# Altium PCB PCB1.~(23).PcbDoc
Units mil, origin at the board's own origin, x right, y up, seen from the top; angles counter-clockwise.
Board outline 6000 x 4000 mil, 2 copper layers (Top Layer, Bottom Layer); 33 components, 28 nets, 150 pads, 4 vias.
Unrouted connection lines stored in the file: 64.
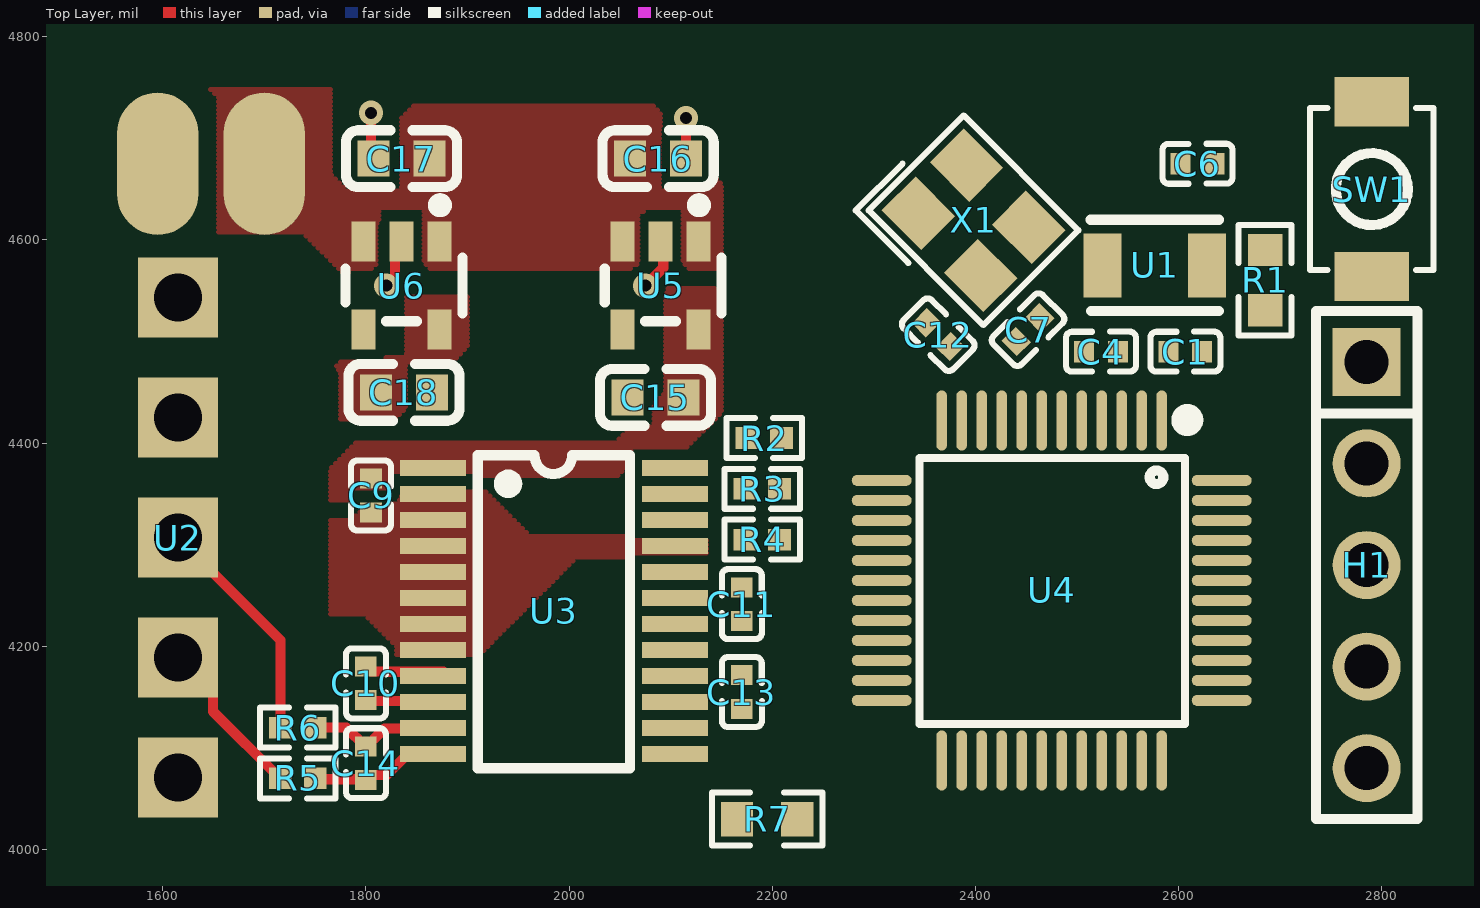
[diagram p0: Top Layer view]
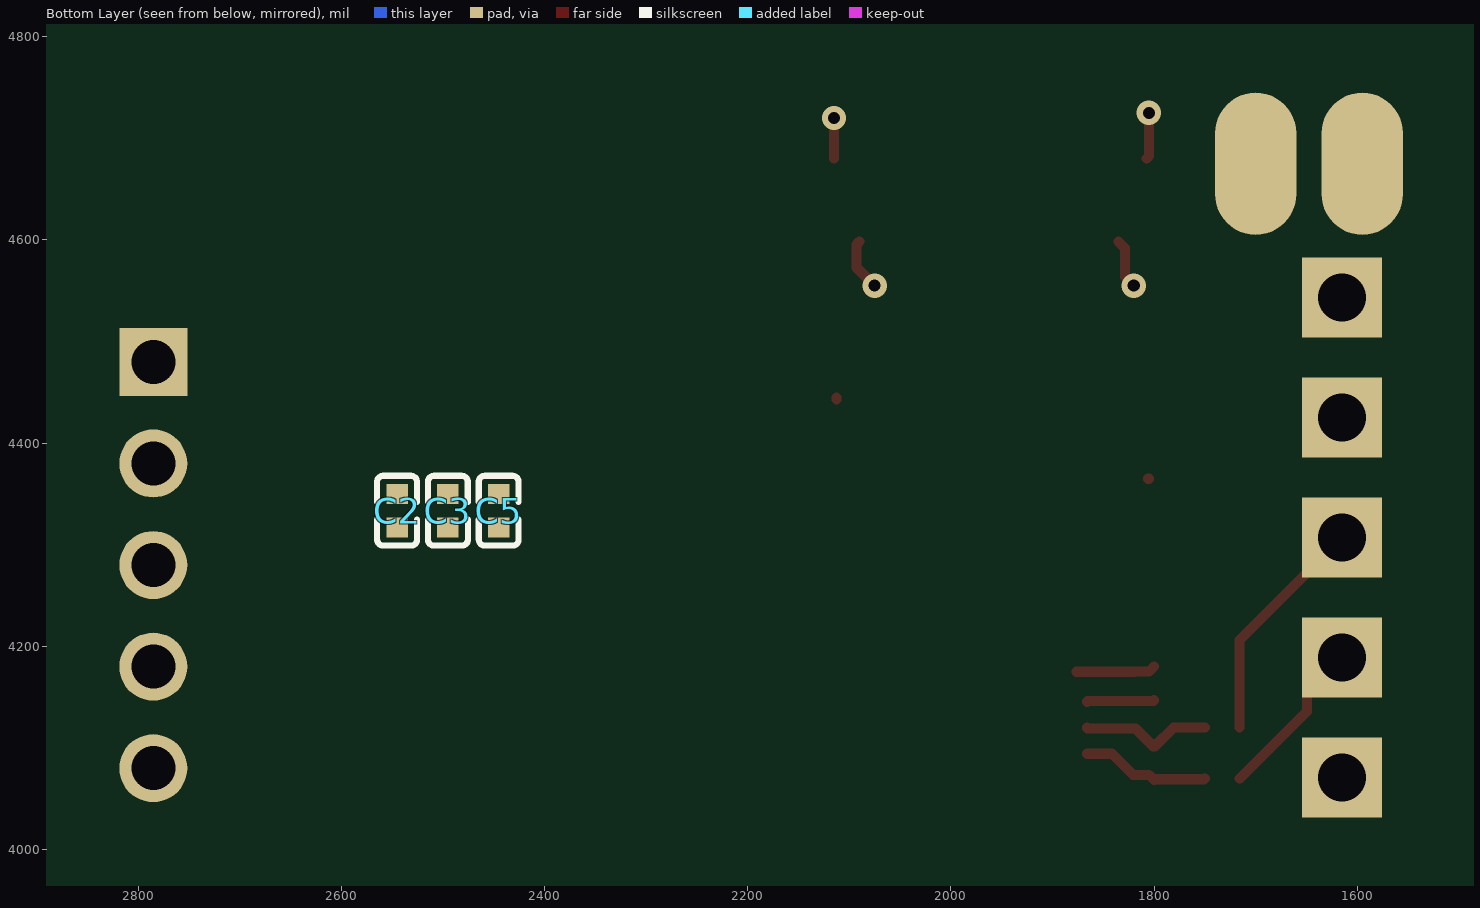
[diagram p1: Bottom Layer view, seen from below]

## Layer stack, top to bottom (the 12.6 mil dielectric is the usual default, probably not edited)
Top Solder: solder mask 0.4, Solder Resist, Dk 3.5
Top Layer: signal copper 1.4
Dielectric 1: dielectric 12.6, FR-4, Dk 4.8
Bottom Layer: signal copper 1.4
Bottom Solder: solder mask 0.4, Solder Resist, Dk 3.5

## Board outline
1000,1000 7000,1000 7000,5000 1000,5000

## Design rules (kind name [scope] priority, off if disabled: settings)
Clearance [All] p1: gap=8 ignorepadtopadclearanceinfootprint=FALSE
ComponentClearance [All] p1: gap=0 collisioncheckmode=3 verticalgap=0 showdistances=FALSE
MinimumSolderMaskSliver [All] p1: minsoldermaskwidth=4
PlaneConnect [All] p1: planeconnectstyle=Direct reliefexpansion=20 reliefentries=4 reliefconductorwidth=10 reliefairgap=10
PolygonConnect [All] p1: connectstyle=Direct reliefconductorwidth=10 reliefentries=4 polygonreliefangle="90 Angle" airgapwidth=10
RoutingVias [All] p1: holewidth=28 width=50 viastyle="Through Hole" minholewidth=28 minwidth=50 maxholewidth=28 maxwidth=50
SilkToSilkClearance [All] p1: silktosilkclearance=5
SilkToSolderMaskClearance [IsPad] p1: minsilkscreentomaskgap=5 clearancetoexposedcopper=TRUE
SolderMaskExpansion [All] p1: expansion=0 istentingtop=FALSE
SupplyNets "Schematic Supply Nets_2" [InNet('6V')] p1: voltage=0.000
SupplyNets "Schematic Supply Nets" [InNet('3V3')] p2: voltage=0.000
SupplyNets "Schematic Supply Nets_4" [InNet('5V')] p3: voltage=0.000
SupplyNets "Schematic Supply Nets_3" [InNet('DGND')] p4: voltage=0.000
SupplyNets "Schematic Supply Nets_1" [InNet('AGND')] p5: voltage=0.000
Width [All] p1: maxlimit=10 minlimit=10 preferedwidth=10
25 further rules are at their usual default settings.

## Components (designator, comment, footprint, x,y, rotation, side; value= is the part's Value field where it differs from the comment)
C1 "cc0402jrnpo9bn220" C0402 2606.54,4490 r180 top value=22pF
C2 "cc0402krx7r7bb104" C0402 2545,4333.46 r270 bottom value=100nF
C3 "cc0402krx7r7bb104" C0402 2495,4333.46 r90 bottom value=100nF
C4 "cc0402jrnpo9bn220" C0402 2523.46,4490 r0 top value=22pF
C5 "cc0402krx7r7bb104" C0402 2445,4333.46 r270 bottom value=100nF
C6 "cc0402krx7r7bb104" C0402 2618.46,4675 r0 top value=100nF
C7 "cc0402jrnpo9bn180" C0402 2451.7,4511.7 r45 top value=18pF
C9 "cc0402krx7r7bb104" C0402 1805,4348.46 r270 top value=100nF
C10 "cc0402krx7r7bb104" C0402 1800,4163.46 r90 top value=100nF
C11 "cc0402krx7r7bb104" C0402 2170,4241.54 r90 top value=100nF
C12 "cc0402jrnpo9bn180" C0402 2363.3,4506.7 r315 top value=18pF
C13 "gcm155r71h103ka55d" C0402 2170,4155 r270 top value=10nF
C14 "gcm155r71h103ka55d" C0402 1800,4085 r270 top value=10nF
C15 "cga0603x5r105k500jt" C0603 2085,4445 r180 top value=1uF
C16 "cga0603x5r105k500jt" C0603 2087.56,4680 r0 top value=1uF
C17 "cga0603x5r105k500jt" C0603 1835,4680 r180 top value=1uF
C18 "cga0603x5r105k500jt" C0603 1837.44,4450 r0 top value=1uF
H1 "pz254v-11-05p" HDR-TH_5P-P2.54-V-M 2785,4280 r270 top
R1 "frc0603f1002ts" R0603 2685,4560.34 r270 top value=10kΩ
R2 "frc0402f47r0ts" R0402 2192.04,4405 r0 top value=47Ω
R3 "frc0402f47r0ts" R0402 2190,4355 r0 top value=47Ω
R4 "frc0402f47r0ts" R0402 2190,4305 r0 top value=47Ω
R5 "frc0402f1000ts" R0402 1732.96,4070 r0 top value=100Ω
R6 "frc0402f1000ts" R0402 1732.96,4120 r0 top value=100Ω
R7 "0603waf0000t5e" R0603 2195,4030 r0 top value=0Ω
SW1 "ts-1088-ar02016" SW-SMD_L3.9-W3.0-P4.45 2790,4650 r90 top
U1 "fc31m2-32.768-ntlnndtl" CRYSTAL-SMD_L3.2-W1.5 2576.5,4575 r180 top value=32.768kHz
U2 "5个焊盘" 5个焊盘 1615,4543.1 r270 top
U3 "ads1232ipwr" TSSOP-24_L7.8-W4.4-P0.65-LS6.4-BL 1985,4235 r270 top
U4 "stm32g031c8t6" LQFP-48_L7.0-W7.0-P0.50-LS9.0-BL 2475,4255 r180 top
U5 "tps7a2033pdbvr" SOT-23-5_L2.9-W1.6-P0.95-LS2.8-BR 2090,4555 r90 top
U6 "tps7a2050pdbvr" SOT-23-5_L2.9-W1.6-P0.95-LS2.8-BR 1835,4555 r90 top
X1 "x32258mob4si" CRYSTAL-SMD_4P-L3.2-W2.5-BL 2398.04,4619.29 r315 top value=8MHz

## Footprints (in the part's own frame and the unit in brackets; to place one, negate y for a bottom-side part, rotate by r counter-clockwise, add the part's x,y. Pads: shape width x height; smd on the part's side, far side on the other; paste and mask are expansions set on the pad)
5个焊盘 [mm]
  rect 2x2 hole 1.2: 1(0,0) 2(3,0) 3(6.001,0) 4(9,0) 5(12,0)
C0402 [mm]
  rect 0.5x0.54 smd: 1(-0.42,0) 2(0.42,0)
  silkscreen extent -0.87,-0.5 0.87,0.5
C0603 [mm]
  rect 0.8x0.9 smd: 1(-0.7,0) 2(0.7,0)
  silkscreen extent -1.39,-0.71 1.39,0.71
CRYSTAL-SMD_4P-L3.2-W2.5-BL [mm]
  rect 1.4x1.2 smd: 1(-1.1,-0.85) 2(1.1,-0.85) 3(1.1,0.85) 4(-1.1,0.85)
  silkscreen extent -2.26,-1.91 2.03,1.68
CRYSTAL-SMD_L3.2-W1.5 [mm]
  rect 0.95x1.6 smd: 1(-1.308,0) 2(1.308,0)
  silkscreen extent -1.6,-1.14 1.6,1.14
HDR-TH_5P-P2.54-V-M [mm]
  rect 1.7x1.7 hole 1.1: 1(-5.08,0)
  round 1.7 hole 1.1: 2(-2.54,0) 3(0,0) 4(2.54,0) 5(5.08,0)
  silkscreen extent -6.35,-1.27 6.35,1.27
LQFP-48_L7.0-W7.0-P0.50-LS9.0-BL [mm]
  oval 0.27x1.5 smd paste+0 mask+0.05: 1(-2.75,-4.25) 2(-2.25,-4.25) 3(-1.75,-4.25) 4(-1.25,-4.25) 5(-0.75,-4.25) 6(-0.25,-4.25) 7(0.25,-4.25) 8(0.75,-4.25) 9(1.25,-4.25) 10(1.75,-4.25) 11(2.25,-4.25) 12(2.75,-4.25) 25(2.75,4.25) 26(2.25,4.25) 27(1.75,4.25) 28(1.25,4.25) 29(0.75,4.25) 30(0.25,4.25) 31(-0.25,4.25) 32(-0.75,4.25) 33(-1.25,4.25) 34(-1.75,4.25) 35(-2.25,4.25) 36(-2.75,4.25)
  oval 1.5x0.27 smd paste+0 mask+0.05: 13(4.25,-2.75) 14(4.25,-2.25) 15(4.25,-1.75) 16(4.25,-1.25) 17(4.25,-0.75) 18(4.25,-0.25) 19(4.25,0.25) 20(4.25,0.75) 21(4.25,1.25) 22(4.25,1.75) 23(4.25,2.25) 24(4.25,2.75) 37(-4.25,2.75) 38(-4.25,2.25) 39(-4.25,1.75) 40(-4.25,1.25) 41(-4.25,0.75) 42(-4.25,0.25) 43(-4.25,-0.25) 44(-4.25,-0.75) 45(-4.25,-1.25) 46(-4.25,-1.75) 47(-4.25,-2.25) 48(-4.25,-2.75)
  silkscreen extent -3.59,-4.46 3.3,3.34
R0402 [mm]
  rect 0.566x0.54 smd paste-100 mask+0.051: 1(-0.433,0) 2(0.433,0)
  silkscreen extent -0.94,-0.5 0.94,0.5
R0603 [mil]
  rect 31.75x34.02 smd paste-3937.01 mask+2: 1(-29.66,0) 2(29.66,0)
  silkscreen extent -55,-26 55,26
SOT-23-5_L2.9-W1.6-P0.95-LS2.8-BR [mm]
  rect 1x0.6 smd paste+0 mask+0.05: 1(1.1,-0.95) 2(1.1,0) 3(1.1,0.95) 4(-1.1,0.95) 5(-1.1,-0.95)
  silkscreen extent -0.89,-1.52 2.16,1.4
SW-SMD_L3.9-W3.0-P4.45 [mm]
  rect 1.23x1.86 smd: 1(-2.185,0) 2(2.185,0)
  silkscreen extent -2.03,-1.54 2.03,1.54
TSSOP-24_L7.8-W4.4-P0.65-LS6.4-BL [mm]
  rect 0.4x1.65 smd: 1(-3.575,-3.023) 2(-2.925,-3.023) 3(-2.275,-3.023) 4(-1.625,-3.023) 5(-0.975,-3.023) 6(-0.325,-3.023) 7(0.325,-3.023) 8(0.975,-3.023) 9(1.625,-3.023) 10(2.275,-3.023) 11(2.925,-3.023) 12(3.575,-3.023) 13(3.575,3.023) 14(2.925,3.023) 15(2.275,3.023) 16(1.625,3.023) 17(0.975,3.023) 18(0.325,3.023) 19(-0.325,3.023) 20(-0.975,3.023) 21(-1.625,3.023) 22(-2.275,3.023) 23(-2.925,3.023) 24(-3.575,3.023)
  silkscreen extent -3.89,-1.91 3.94,1.91

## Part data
C1 C4: "容值:22pF;精度:±5%;额定电压:50V;温度系数:NP0;", JLCPCB Part Class="Extended Part", LCSC Part Name="22pF ±5% 50V", Manufacturer=YAGEO(国巨), ManufacturerPart=CC0402JRNPO9BN220, Temperature Coefficient=NP0, Tolerance=±5%, Voltage Rating=50V
C2 C3 C5 C6 C9 C10 C11: "容值:100nF;精度:±10%;额定电压:16V;温度系数:X7R;", JLCPCB Part Class="Extended Part", LCSC Part Name="100nF ±10% 16V", Manufacturer=YAGEO(国巨), ManufacturerPart=CC0402KRX7R7BB104, Temperature Coefficient=X7R, Tolerance=±10%, Voltage Rating=16V
C7 C12: "容值:18pF;精度:±5%;额定电压:50V;温度系数:NP0;", JLCPCB Part Class="Extended Part", LCSC Part Name="18pF ±5% 50V", Manufacturer=YAGEO(国巨), ManufacturerPart=CC0402JRNPO9BN180, Temperature Coefficient=NP0, Tolerance=±5%, Voltage Rating=50V
C13 C14: "容值:10nF;精度:±10%;额定电压:50V;温度系数:X7R;", JLCPCB Part Class="Extended Part", LCSC Part Name="10nF ±10% 50V", Manufacturer=muRata(村田), ManufacturerPart=GCM155R71H103KA55D, Temperature Coefficient=X7R, Tolerance=±10%, Voltage Rating=50V
C15 C16 C17 C18: "容值:1uF;精度:±10%;额定电压:50V;温度系数:X5R;", JLCPCB Part Class="Extended Part", LCSC Part Name="1uF ±10% 50V 停产", Manufacturer=HRE(芯声), ManufacturerPart=CGA0603X5R105K500JT, Temperature Coefficient=X5R, Tolerance=±10%, Voltage Rating=50V
H1: "插针结构:1x5P;间距:2.54mm;行距:-;圆针/方针:方针;安装方式:直插;排数:单排;总PIN位数:5P;额定电流:3A;额定电压:250V;配合针长度:6mm;塑高:2.5mm;端接针长度:3mm;触头材质:黄铜;触头镀层:-;工作温度:-40℃~+105℃;颜色:黑色;", Color=黑色, Current Rating=3A, JLCPCB Part Class="Extended Part", LCSC Part Name="1x5P 间距:2.54mm 方针 直插", Manufacturer=XFCN(兴飞), ManufacturerPart=PZ254V-11-05P, Operating Temperature=-40℃~+105℃, Voltage Rating (Max)=250V
R1: "电阻类型:厚膜电阻;阻值:10kΩ;精度:±1%;功率:100mW;工作电压:75V;温度系数:±100ppm/℃;", JLCPCB Part Class="Extended Part", LCSC Part Name="10kΩ ±1% 100mW 厚膜电阻", Manufacturer=FOJAN(富捷), ManufacturerPart=FRC0603F1002TS, Operating Temperature=-55℃~+155℃, Power(Watts)=100mW, Temperature Coefficient=±100ppm/℃, Tolerance=±1%, Voltage-Supply(Max)=75V
R2 R3 R4: "电阻类型:厚膜电阻;阻值:47Ω;精度:±1%;功率:62.5mW;工作电压:50V;温度系数:±100ppm/℃;", JLCPCB Part Class="Extended Part", LCSC Part Name="47Ω ±1% 62.5mW 厚膜电阻", Manufacturer=FOJAN(富捷), ManufacturerPart=FRC0402F47R0TS, Operating Temperature=-55℃~+155℃, Power(Watts)=62.5mW, Temperature Coefficient=±100ppm/℃, Tolerance=±1%, Voltage-Supply(Max)=50V
R5 R6: "电阻类型:厚膜电阻;阻值:100Ω;精度:±1%;功率:62.5mW;工作电压:50V;温度系数:±100ppm/℃;", JLCPCB Part Class="Extended Part", LCSC Part Name="100Ω ±1% 62.5mW 厚膜电阻", Manufacturer=FOJAN(富捷), ManufacturerPart=FRC0402F1000TS, Operating Temperature=-55℃~+155℃, Power(Watts)=62.5mW, Temperature Coefficient=±100ppm/℃, Tolerance=±1%, Voltage-Supply(Max)=50V
R7: "电阻类型:厚膜电阻;阻值:0Ω;精度:±1%;功率:100mW;工作电压:75V;温度系数:-;", JLCPCB Part Class="Basic Part", LCSC Part Name="0Ω ±1% 100mW 厚膜电阻", Manufacturer=UNI-ROYAL(厚声), ManufacturerPart=0603WAF0000T5E, Operating Temperature=-55℃~+155℃, Power(Watts)=100mW, Temperature Coefficient=-, Tolerance=±1%, Voltage-Supply(Max)=75V
SW1: "电路结构:单刀单掷;按钮形状:圆形按钮;作用力:1.6N;安装方式:立贴;开关长度:3.9mm;开关宽度:3mm;开关高度:2mm;带支架:不带支架;触点电流:50mA;额定电压:12V;带灯:-;工作寿命:10万次;", Actuator/Cap Color=黑色, Contact Current=50mA, IP Rating=-, JLCPCB Part Class="Basic Part", LCSC Part Name="3.9*3*2mm 立贴 轻触开关", Manufacturer=XUNPU(讯普), ManufacturerPart=TS-1088-AR02016, Operating Force=1.6N, Operating Temperature=-30℃~+80℃, Voltage Rating=12V
U1: "晶振类型:贴片晶振;频率:32.768kHz;常温频差:±10ppm;负载电容:12.5pF;频率稳定度:±10ppm;", Equivalent Series Resistance(ESR)=70kΩ, Frequency Stability=±10ppm, JLCPCB Part Class="Extended Part", LCSC Part Name="3215 2P 32.768kHz 12.5pF ±10ppm -40~+85℃(±10ppm)", Load Capacitance=12.5pF, Manufacturer=HCI(杭晶), ManufacturerPart=FC31M2-32.768-NTLNNDTL, Operating Temperature=-40℃~+85℃
U3: "分辨率(位):24;采样率:10Hz;工作电压:2.7V~5.3V;接口类型:SPI;", Clock Frequency=4.9152MHz；200kHz~8MHz, JLCPCB Part Class="Extended Part", LCSC Part Name="用于桥式传感器的24bit 模数转换器", Manufacturer=TI(德州仪器), ManufacturerPart=ADS1232IPWR, Operating Temperature=-40℃~+105℃, Quiescent Current (Iq)=1.3uA, Temperature Sensors=内置, Voltage - Supply=2.7V~5.3V, Voltage Reference=外置, Voltage Reference Drift=-
U4: "CPU内核:ARM Cortex-M0+;CPU最大主频:64MHz;CPU位数:32 Bit;", JLCPCB Part Class="Extended Part", LCSC Part Name="主流Arm Cortex-M0+ MCU，具有64 KB Flash存储器、8 KB RAM、64 MHz CPU、2x USART、定时器、ADC和通信接口，1.7-3.6V", Manufacturer=ST(意法半导体), ManufacturerPart=STM32G031C8T6, Operating Temperature=-40℃~+85℃, Voltage - Supply=1.7V~3.6V
U5: "输出类型:固定;最大输入电压:6V;输出电压:3.3V;输出电流:300mA;输出极性:正极;", Dropout Voltage=140mV@(300mA), JLCPCB Part Class="Extended Part", LCSC Part Name="具有高 PSRR 的 300mA、超低噪声、低 IQ、低压降 (LDO) 线性稳压器", Manufacturer=TI(德州仪器), ManufacturerPart=TPS7A2033PDBVR, Maximum Input Voltage=6V, Operating Temperature=-40℃~+125℃@(Tj), Output Current=300mA, Output Voltage=3.3V, standby current=15uA
U6: "输出极性:正极;工作电压:6V;输出电压:5V;输出电流:300mA;电源纹波抑制比(PSRR):65dB@(100Hz);输出类型:固定;", JLCPCB Part Class="Extended Part", LCSC Part Name="800mV~5.5V 300mA 6V", Manufacturer=TI(德州仪器), ManufacturerPart=TPS7A2050PDBVR, Operating Temperature=-40℃~+125℃@(Tj), Output Current=300mA, Output Voltage=5V, Power Supply Rejection Ratio (PSRR)=65dB@(100Hz), standby current=6.5uA, Voltage - Supply=6V, Voltage Dropout=140mV@(300mA)
X1: "晶振类型:贴片晶振;频率:8MHz;常温频差:±10ppm;负载电容:12pF;频率稳定度:±20ppm;", Equivalent Series Resistance(ESR)=180Ω, Frequency Stability=±20ppm, JLCPCB Part Class="Extended Part", LCSC Part Name="YSX321SL 8MHZ 4P 3225 12PF ±10PPM -40~85℃ (±20PPM)", Load Capacitance=12pF, Manufacturer=YXC(扬兴晶振), ManufacturerPart=X32258MOB4SI, Normal temperature Frequency Tolerance=±10ppm, Operating Temperature=-40℃~+85℃

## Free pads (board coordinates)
  oval 80x140 all layers, no hole: 7(1595,4675) 7(1700,4675)

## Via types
v1: diameter 24, hole 12, Top Layer to Bottom Layer, tented both sides, 4 vias

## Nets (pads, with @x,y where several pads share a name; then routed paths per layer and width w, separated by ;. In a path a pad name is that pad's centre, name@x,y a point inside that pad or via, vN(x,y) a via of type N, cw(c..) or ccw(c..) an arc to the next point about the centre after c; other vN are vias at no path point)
3V3: C2.1 C3.2 C5.1 C9.1 C15.1 H1.1 R1.2 U3.1 U3.19 U3.20 U4.4 U4.5 U4.6 U5.5 | length 2.8
  Top Layer w10: C9.1 C9.1@1805.79,4365 ; C15.1@2112.56,4443.03 C15.1
5V: C11.1 C13.1 C18.1 U2.1 U3.16 U3.18 U6.5
6V: C16.1 C17.1 pad.7@1700,4675 U5.1 U5.3 U6.1 U6.3
AGND: C11.2 C13.2 R7.1 U2.2 U2.5 U3.13 U3.14 U3.15 U3.17
AINN1: R5.1 U2.4 | length 160.9
  Top Layer w10: U2.4 1649.37,4154.39 1649.37,4136.04 1715.41,4070 R5.1
AINP1: R6.1 U2.3 | length 228.7
  Top Layer w10: U2.3 1715.92,4205.94 R6.1
DGND: C1.1 C2.2 C3.1 C4.1 C5.2 C6.1 C7.2 C9.2 C12.1 C15.2 C16.2 C17.2 C18.2 H1.2 pad.7@1595,4675 R7.2 SW1.1 U3.2 U3.3 U3.4 U3.5 U3.6 U3.7 U3.8 U3.21 U4.7 U5.2 U6.2 X1.2 X1.4 | length 187.3
  Top Layer w10: v1(1805,4725) 1805,4682.44 C17.2 ; v1(1820,4555) 1828.62,4563.62 1828.62,4591.92 U6.2 ; v1(2075,4555) 2092.68,4572.68 2092.68,4595.63 U5.2 ; v1(2115,4720) 2115.12,4719.88 C16.2
DOUT: R2.2 U4.19
NetC1_2: C1.2 U1.2 U4.2
NetC4_2: C4.2 U1.1 U4.3
NetC7_1: C7.1 U4.8 X1.3
NetC10_1: C10.1 U3.10 | length 66.6
  Top Layer w10: C10.1 1800.74,4146.18 1865.26,4146.18 U3.10
NetC10_2: C10.2 U3.9 | length 78.3
  Top Layer w10: C10.2 1804.84,4175.16 1819.84,4175.16 1820,4175 U3.9@1876.23,4175
NetC12_2: C12.2 U4.9 X1.1
NetC14_1: C14.1 R6.2 U3.11 | length 131.2
  Top Layer w10: R6.2 1780.75,4120 1799.21,4101.54 C14.1 1800.79,4101.54 1818.52,4119.27 1865.43,4119.27 U3.11
NetC14_2: C14.2 R5.2 U3.12 | length 127.3
  Top Layer w10: R5.2 1750.77,4069.23 1799.23,4069.23 C14.2 1804.84,4073.3 1820.44,4073.3 1841.39,4094.26 U3.12
NetR2_1: R2.1 U3.24
NetR3_1: R3.1 U3.23
NetR4_1: R4.1 U3.22
NRST: C6.2 H1.5 R1.1 SW1.2 U4.10
PDWN: R4.2 U4.21
SCLK: R3.2 U4.20
SWCLK: H1.3 U4.36
SWDIO: H1.4 U4.35
USART1_RX: U4.32
USART1_TX: U4.29
USART2_RX: U4.14
USART2_TX: U4.13
pads on no net: U4.1 U4.11 U4.12 U4.15 U4.16 U4.17 U4.18 U4.22 U4.23 U4.24 U4.25 U4.26 U4.27 U4.28 U4.30 U4.31 U4.33 U4.34 U4.37 U4.38 U4.39 U4.40 U4.41 U4.42 U4.43 U4.44 U4.45 U4.46 U4.47 U4.48 U5.4 U6.4

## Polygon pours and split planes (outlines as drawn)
DGND on Top Layer "NONET_L-01_P-001" (hatched Horizontal grid 4 track 5, remove dead copper, pour order 5): 1765,4340 1820,4340 1832.5,4352.5 1830,4355 1830,4365 1905,4365 1960,4310 2135,4310 2135,4290 2130,4285 2005,4285 1905,4185 1830,4185 1830,4200 1800,4230 1765,4230
6V on Top Layer "NONET_L-01_P-001" (hatched Horizontal grid 4 track 5, remove dead copper, pour order 3): 1645,4750 1655,4740 1655,4605 1740,4605 1780,4565 1785,4570 1810,4570 1810,4615 1820,4625 1855,4625 1855,4580 1865,4570 2070,4570 2070,4625 2075,4630 2105,4630 2105,4585 2120,4570 2150,4570 2150,4655 2140,4665 2090,4665 2090,4725 2080,4735 1850,4735 1835,4720 1835,4650 1780,4650 1765,4665 1765,4750
3V3 on Top Layer "NONET_L-01_P-001" (hatched Horizontal grid 4 track 5, remove dead copper, pour order 2): 2095,4555 2095,4450 2045,4400 1790,4400 1765,4375 1765,4340 1820,4340 1845,4365 2045,4365 2070,4390 2110,4390 2150,4430 2150,4545 2140,4555
5V on Top Layer "NONET_L-01_P-001" (hatched Horizontal grid 4 track 5, remove dead copper, pour order 1): 1840,4545 1840,4485 1780,4485 1770,4475 1775,4470 1775,4420 1825,4420 1845,4440 1845,4475 1880,4475 1900,4495 1900,4545

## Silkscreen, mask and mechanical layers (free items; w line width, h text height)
Mechanical 1:
  lines w10: 1515,3965 2870,3965 2870,4765 1515,4765 1515,3965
